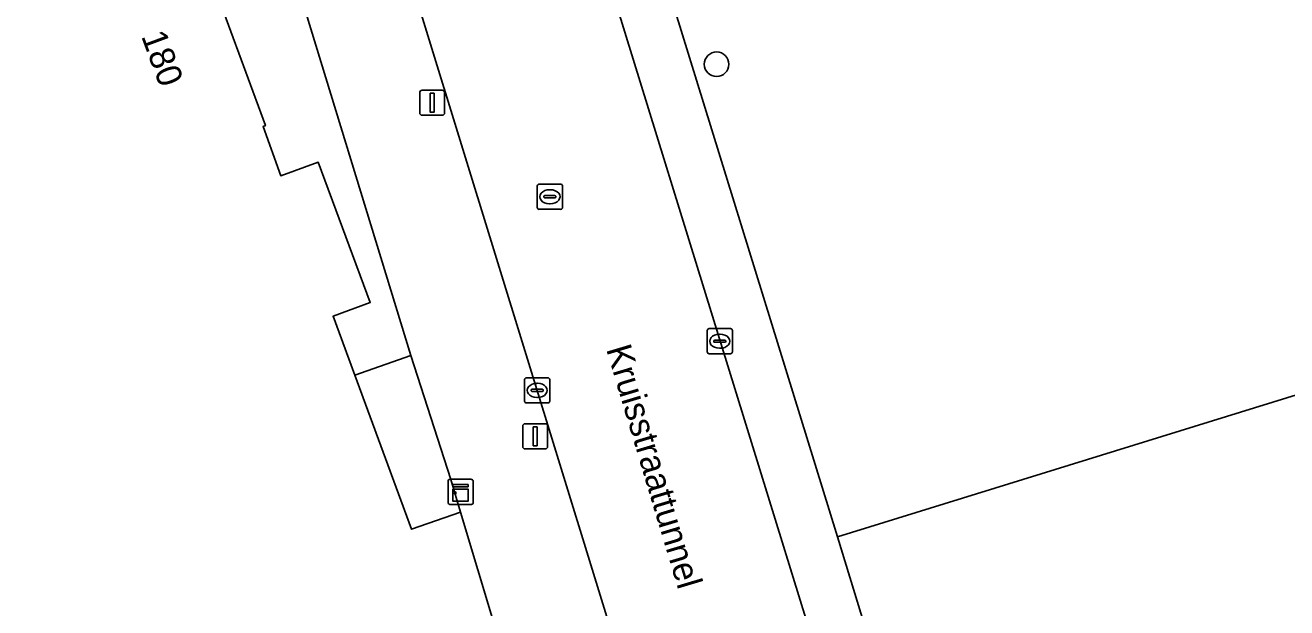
# Model space of a CAD drawing. Extents: x 160806 to 161707, y 383696 to 384148.
# Drawn here: x 161082.8 to 161133, y 383972.9 to 383996.1 of the extents above; entities that cross this region are included whole.
import ezdxf

# ---------------------------------------------------------------- set-up
doc = ezdxf.new("R2010")
doc.units = 0
for name, color, linetype in [('IMGEO_Boom', 7, 'Continuous'), ('IMGEO_Erf', 7, 'Continuous'), ('IMGEO_Fietspad_gesloten', 7, 'Continuous'), ('IMGEO_Groenvoorziening', 7, 'Continuous'), ('IMGEO_Kast', 7, 'Continuous'), ('IMGEO_Kolk', 7, 'Continuous'), ('IMGEO_Lichtmast', 7, 'Continuous'), ('IMGEO_Muur', 7, 'Continuous'), ('IMGEO_Openbare_ruimte_label', 7, 'Continuous'), ('IMGEO_Pand', 7, 'Continuous'), ('IMGEO_Pand_nummerreeks', 7, 'Continuous'), ('IMGEO_Rioolput', 7, 'Continuous'), ('IMGEO_Voetpad_open', 7, 'Continuous')]:
    doc.layers.add(name, color=color, linetype=linetype)

msp = doc.modelspace()

# ---------------------------------------------------------------- linework, layer by layer
at = {"layer": 'IMGEO_Boom'}
msp.add_circle((161110.294, 383994.548), 0.489, dxfattribs=at)
at = {"layer": 'IMGEO_Erf'}
msp.add_lwpolyline([(161107.408, 384024.109), (161106.928, 384021.186), (161106.784, 384020.283), (161105.349, 384011.638), (161106.437, 384005.758), (161105.911, 384005.605), (161107.16, 384001.487), (161115.101, 383975.756), (161174.941, 383994.27), (161177.371, 383986.415), (161171.512, 383984.603), (161172.182, 383982.438), (161174.353, 383983.11), (161177.012, 383974.513), (161143.485, 383964.14), (161143.98, 383962.542), (161149.045, 383964.109), (161151.693, 383955.552), (161154.338, 383947.003), (161157.491, 383936.811), (161157.865, 383935.602), (161130.022, 383926.988)], dxfattribs=at)
at = {"layer": 'IMGEO_Fietspad_gesloten'}
msp.add_lwpolyline([(161096.658, 384002.717), (161097.481, 384000.05), (161112.041, 383952.737), (161119.258, 383954.945), (161104.758, 384001.93), (161103.731, 384005.273), (161103.627, 384007.38)], dxfattribs=at)
at = {"layer": 'IMGEO_Groenvoorziening'}
msp.add_lwpolyline([(161098.143, 383982.971), (161095.914, 383982.188), (161098.17, 383976.057), (161100.111, 383976.738), (161099.73, 383978.043)], close=True, dxfattribs=at)
at = {"layer": 'IMGEO_Kast'}
for p, q in [((161099.695, 383978.044), (161100.536, 383978.044)), ((161100.536, 383978.044), (161099.695, 383978.044)), ((161099.62, 383977.119), (161099.62, 383977.96)), ((161099.62, 383977.96), (161099.62, 383977.119)), ((161100.62, 383977.969), (161100.62, 383977.128)), ((161100.62, 383977.128), (161100.62, 383977.969)), ((161100.545, 383977.044), (161099.704, 383977.044)), ((161099.704, 383977.044), (161100.545, 383977.044))]:
    msp.add_line(p, q, dxfattribs=at)
for points in [[(161099.815, 383977.834), (161100.415, 383977.834), (161100.415, 383977.749), (161099.815, 383977.749), (161099.815, 383977.834)], [(161099.815, 383977.659), (161100.415, 383977.659), (161100.415, 383977.17), (161099.815, 383977.17), (161099.815, 383977.659)]]:
    msp.add_lwpolyline(points, dxfattribs=at)
msp.add_circle((161099.899, 383977.508), 0.0377, dxfattribs=at)
for centre, start, end in [((161099.698, 383977.966), 92.4484, 184.2845), ((161099.698, 383977.966), 92.4484, 184.2845), ((161100.542, 383977.966), 2.4484, 94.2845), ((161100.542, 383977.966), 2.4484, 94.2845), ((161099.698, 383977.122), 182.4484, 274.2845), ((161099.698, 383977.122), 182.4484, 274.2845), ((161100.542, 383977.122), 272.4484, 4.2845), ((161100.542, 383977.122), 272.4484, 4.2845)]:
    msp.add_arc(centre, 0.0779, start, end, dxfattribs=at)
at = {"layer": 'IMGEO_Kolk'}
for p, q in [((161109.994, 383984.035), (161110.846, 383984.035)), ((161109.919, 383983.109), (161109.919, 383983.961)), ((161110.178, 383983.529), (161110.178, 383983.541)), ((161110.616, 383983.492), (161110.218, 383983.492)), ((161110.221, 383983.578), (161110.619, 383983.578)), ((161110.407, 383983.815), (161110.432, 383983.815)), ((161110.662, 383983.541), (161110.662, 383983.529)), ((161110.92, 383983.961), (161110.92, 383983.109)), ((161110.846, 383983.035), (161109.994, 383983.035)), ((161110.43, 383983.255), (161110.405, 383983.255)), ((161102.662, 383981.155), (161102.662, 383982.007)), ((161102.737, 383982.081), (161103.589, 383982.081)), ((161103.663, 383982.007), (161103.663, 383981.155)), ((161102.921, 383981.575), (161102.921, 383981.587)), ((161103.359, 383981.538), (161102.961, 383981.538)), ((161102.964, 383981.624), (161103.362, 383981.624)), ((161103.15, 383981.861), (161103.175, 383981.861)), ((161103.405, 383981.587), (161103.405, 383981.575)), ((161103.589, 383981.081), (161102.737, 383981.081)), ((161103.173, 383981.301), (161103.148, 383981.301))]:
    msp.add_line(p, q, dxfattribs=at)
for points in [[(161109.994, 383984.035), (161110.846, 383984.035)], [(161109.919, 383983.109), (161109.919, 383983.961)], [(161110.92, 383983.961), (161110.92, 383983.109)], [(161110.846, 383983.035), (161109.994, 383983.035)], [(161102.662, 383981.155), (161102.662, 383982.007)], [(161102.737, 383982.081), (161103.589, 383982.081)], [(161103.663, 383982.007), (161103.663, 383981.155)], [(161103.589, 383981.081), (161102.737, 383981.081)]]:
    msp.add_lwpolyline(points, dxfattribs=at)
for centre, radius, start, end in [((161109.996, 383983.959), 0.0765, 91.552, 178.448), ((161109.996, 383983.959), 0.0765, 91.552, 178.448), ((161110.844, 383983.959), 0.0765, 1.552, 88.448), ((161110.844, 383983.959), 0.0765, 1.552, 88.448), ((161110.218, 383983.538), 0.0403, 85.8775, 175.7526), ((161110.215, 383983.528), 0.0366, 178.938, 274.7102), ((161110.619, 383983.535), 0.043, 264.8664, 352.4533), ((161110.623, 383983.54), 0.0386, 1.7309, 96.639), ((161109.996, 383983.111), 0.0765, 181.552, 268.448), ((161109.996, 383983.111), 0.0765, 181.552, 268.448), ((161110.844, 383983.111), 0.0765, 271.552, 358.448), ((161110.844, 383983.111), 0.0765, 271.552, 358.448), ((161102.739, 383982.005), 0.0765, 91.552, 178.448), ((161102.739, 383982.005), 0.0765, 91.552, 178.448), ((161103.587, 383982.005), 0.0765, 1.552, 88.448), ((161103.587, 383982.005), 0.0765, 1.552, 88.448), ((161102.961, 383981.584), 0.0403, 85.8775, 175.7526), ((161102.958, 383981.574), 0.0366, 178.938, 274.7102), ((161103.362, 383981.581), 0.043, 264.8664, 352.4533), ((161103.366, 383981.586), 0.0386, 1.7309, 96.639), ((161102.739, 383981.157), 0.0765, 181.552, 268.448), ((161102.739, 383981.157), 0.0765, 181.552, 268.448), ((161103.587, 383981.157), 0.0765, 271.552, 358.448), ((161103.587, 383981.157), 0.0765, 271.552, 358.448)]:
    msp.add_arc(centre, radius, start, end, dxfattribs=at)
for centre, major_axis, ratio, start_param, end_param in [((161110.406, 383983.535), (-0.387, 0.002), 0.722429, 4.712389, 7.853982), ((161110.431, 383983.535), (-0.39, 0.002), 0.717154, 1.570796, 4.712389), ((161103.149, 383981.581), (-0.387, 0.002), 0.722429, 4.712389, 7.853982), ((161103.174, 383981.581), (-0.39, 0.002), 0.717154, 1.570796, 4.712389)]:
    msp.add_ellipse(centre, major_axis=major_axis, ratio=ratio, start_param=start_param, end_param=end_param, dxfattribs=at)
at = {"layer": 'IMGEO_Lichtmast'}
for p, q in [((161098.491, 383992.616), (161098.491, 383993.416)), ((161098.491, 383993.416), (161098.491, 383992.616)), ((161098.591, 383993.516), (161099.381, 383993.516)), ((161099.381, 383993.516), (161098.591, 383993.516)), ((161099.481, 383993.416), (161099.481, 383992.616)), ((161099.481, 383992.616), (161099.481, 383993.416)), ((161099.381, 383992.516), (161098.591, 383992.516)), ((161098.591, 383992.516), (161099.381, 383992.516)), ((161102.586, 383979.353), (161102.586, 383980.153)), ((161102.586, 383980.153), (161102.586, 383979.353)), ((161102.686, 383980.253), (161103.476, 383980.253)), ((161103.476, 383980.253), (161102.686, 383980.253)), ((161103.576, 383980.153), (161103.576, 383979.353)), ((161103.576, 383979.353), (161103.576, 383980.153)), ((161103.476, 383979.253), (161102.686, 383979.253)), ((161102.686, 383979.253), (161103.476, 383979.253))]:
    msp.add_line(p, q, dxfattribs=at)
for points in [[(161098.911, 383993.391), (161099.061, 383993.391), (161099.061, 383992.641), (161098.911, 383992.641), (161098.911, 383993.391)], [(161103.006, 383980.128), (161103.156, 383980.128), (161103.156, 383979.378), (161103.006, 383979.378), (161103.006, 383980.128)]]:
    msp.add_lwpolyline(points, dxfattribs=at)
for centre, start, end in [((161098.591, 383993.416), 90, 180), ((161098.591, 383993.416), 90, 180), ((161099.381, 383993.416), 0, 90), ((161099.381, 383993.416), 360, 90), ((161098.591, 383992.616), 180, 270), ((161098.591, 383992.616), 180, 270), ((161099.381, 383992.616), 270, 0), ((161099.381, 383992.616), 270, 0), ((161102.686, 383980.153), 90, 180), ((161102.686, 383980.153), 90, 180), ((161103.476, 383980.153), 0, 90), ((161103.476, 383980.153), 360, 90), ((161102.686, 383979.353), 180, 270), ((161102.686, 383979.353), 180, 270), ((161103.476, 383979.353), 270, 0), ((161103.476, 383979.353), 270, 0)]:
    msp.add_arc(centre, 0.1, start, end, dxfattribs=at)
at = {"layer": 'IMGEO_Muur'}
msp.add_lwpolyline([(161107.16, 384001.487), (161115.101, 383975.756)], dxfattribs=at)
at = {"layer": 'IMGEO_Pand'}
msp.add_lwpolyline([(161107.531, 383952.042), (161100.111, 383976.738), (161098.17, 383976.057), (161095.914, 383982.188), (161095.052, 383984.53), (161096.529, 383985.078), (161094.462, 383990.653), (161092.972, 383990.116), (161092.264, 383992.069), (161092.359, 383992.107), (161090.795, 383996.359), (161085.268, 384011.384), (161085.223, 384011.506), (161076.291, 384008.231)], dxfattribs=at)
msp.add_lwpolyline([(161154.338, 383947.003), (161151.693, 383955.552), (161149.045, 383964.109), (161143.98, 383962.542), (161143.485, 383964.14), (161177.012, 383974.513), (161174.353, 383983.11), (161172.182, 383982.438), (161171.512, 383984.603), (161177.371, 383986.415), (161174.941, 383994.27), (161115.101, 383975.756), (161121.28, 383955.564), (161129.654, 383928.199), (161130.022, 383926.988), (161157.865, 383935.602), (161157.491, 383936.811)], close=True, dxfattribs=at)
at = {"layer": 'IMGEO_Rioolput'}
for p, q in [((161103.167, 383988.853), (161103.167, 383989.705)), ((161103.242, 383989.779), (161104.094, 383989.779)), ((161103.655, 383989.559), (161103.68, 383989.559)), ((161104.168, 383989.705), (161104.168, 383988.853)), ((161103.426, 383989.273), (161103.426, 383989.285)), ((161103.864, 383989.236), (161103.466, 383989.236)), ((161103.469, 383989.322), (161103.867, 383989.322)), ((161103.91, 383989.285), (161103.91, 383989.273)), ((161104.094, 383988.779), (161103.242, 383988.779)), ((161103.678, 383988.999), (161103.653, 383988.999))]:
    msp.add_line(p, q, dxfattribs=at)
for points in [[(161103.167, 383988.853), (161103.167, 383989.705)], [(161103.242, 383989.779), (161104.094, 383989.779)], [(161104.168, 383989.705), (161104.168, 383988.853)], [(161104.094, 383988.779), (161103.242, 383988.779)]]:
    msp.add_lwpolyline(points, dxfattribs=at)
for centre, radius, start, end in [((161103.244, 383989.703), 0.0765, 91.552, 178.448), ((161103.244, 383989.703), 0.0765, 91.552, 178.448), ((161104.092, 383989.703), 0.0765, 1.552, 88.448), ((161104.092, 383989.703), 0.0765, 1.552, 88.448), ((161103.466, 383989.282), 0.0403, 85.8775, 175.7526), ((161103.463, 383989.272), 0.0366, 178.938, 274.7102), ((161103.867, 383989.279), 0.043, 264.8664, 352.4533), ((161103.871, 383989.284), 0.0386, 1.7309, 96.639), ((161103.244, 383988.855), 0.0765, 181.552, 268.448), ((161103.244, 383988.855), 0.0765, 181.552, 268.448), ((161104.092, 383988.855), 0.0765, 271.552, 358.448), ((161104.092, 383988.855), 0.0765, 271.552, 358.448)]:
    msp.add_arc(centre, radius, start, end, dxfattribs=at)
for centre, major_axis, ratio, start_param, end_param in [((161103.654, 383989.279), (-0.387, 0.002), 0.722429, 4.712389, 7.853982), ((161103.679, 383989.279), (-0.39, 0.002), 0.717154, 1.570796, 4.712389)]:
    msp.add_ellipse(centre, major_axis=major_axis, ratio=ratio, start_param=start_param, end_param=end_param, dxfattribs=at)
at = {"layer": 'IMGEO_Voetpad_open'}
for points in [[(161097.884, 384019.582), (161099.091, 384024.316), (161087.151, 384018.873), (161098.143, 383982.971), (161099.73, 383978.043), (161100.111, 383976.738), (161107.531, 383952.042), (161107.6, 383951.813), (161107.72, 383951.415), (161112.041, 383952.737), (161097.481, 384000.05), (161096.658, 384002.717)], [(161115.101, 383975.756), (161107.16, 384001.487), (161105.911, 384005.605), (161106.437, 384005.758), (161105.349, 384011.638), (161106.784, 384020.283), (161106.928, 384021.186), (161107.408, 384024.109)], [(161103.627, 384007.38), (161103.731, 384005.273), (161104.758, 384001.93), (161119.258, 383954.945), (161121.28, 383955.564), (161115.101, 383975.756)]]:
    msp.add_lwpolyline(points, dxfattribs=at)
msp.add_lwpolyline([(161096.529, 383985.078), (161095.052, 383984.53), (161095.914, 383982.188), (161098.143, 383982.971), (161087.151, 384018.873), (161052.328, 384002.909), (161046.899, 384000.438), (161047.022, 384000.146), (161045.113, 383999.3), (161044.796, 383999.32), (161046.766, 383994.877), (161049.694, 383995.956), (161048.417, 383999.403), (161075.766, 384009.535), (161076.291, 384008.231), (161085.223, 384011.506), (161085.268, 384011.384), (161090.795, 383996.359), (161092.359, 383992.107), (161092.264, 383992.069), (161092.972, 383990.116), (161094.462, 383990.653)], close=True, dxfattribs=at)

# ---------------------------------------------------------------- texts
at = {"layer": 'IMGEO_Openbare_ruimte_label'}
msp.add_text('Kruisstraattunnel', height=1, rotation=286.6773, dxfattribs=at).set_placement((161105.897, 383983.228))
at = {"layer": 'IMGEO_Pand_nummerreeks'}
msp.add_text('180', height=1, rotation=290.3169, dxfattribs=at).set_placement((161087.412, 383995.668))

doc.saveas('drawing.dxf')
